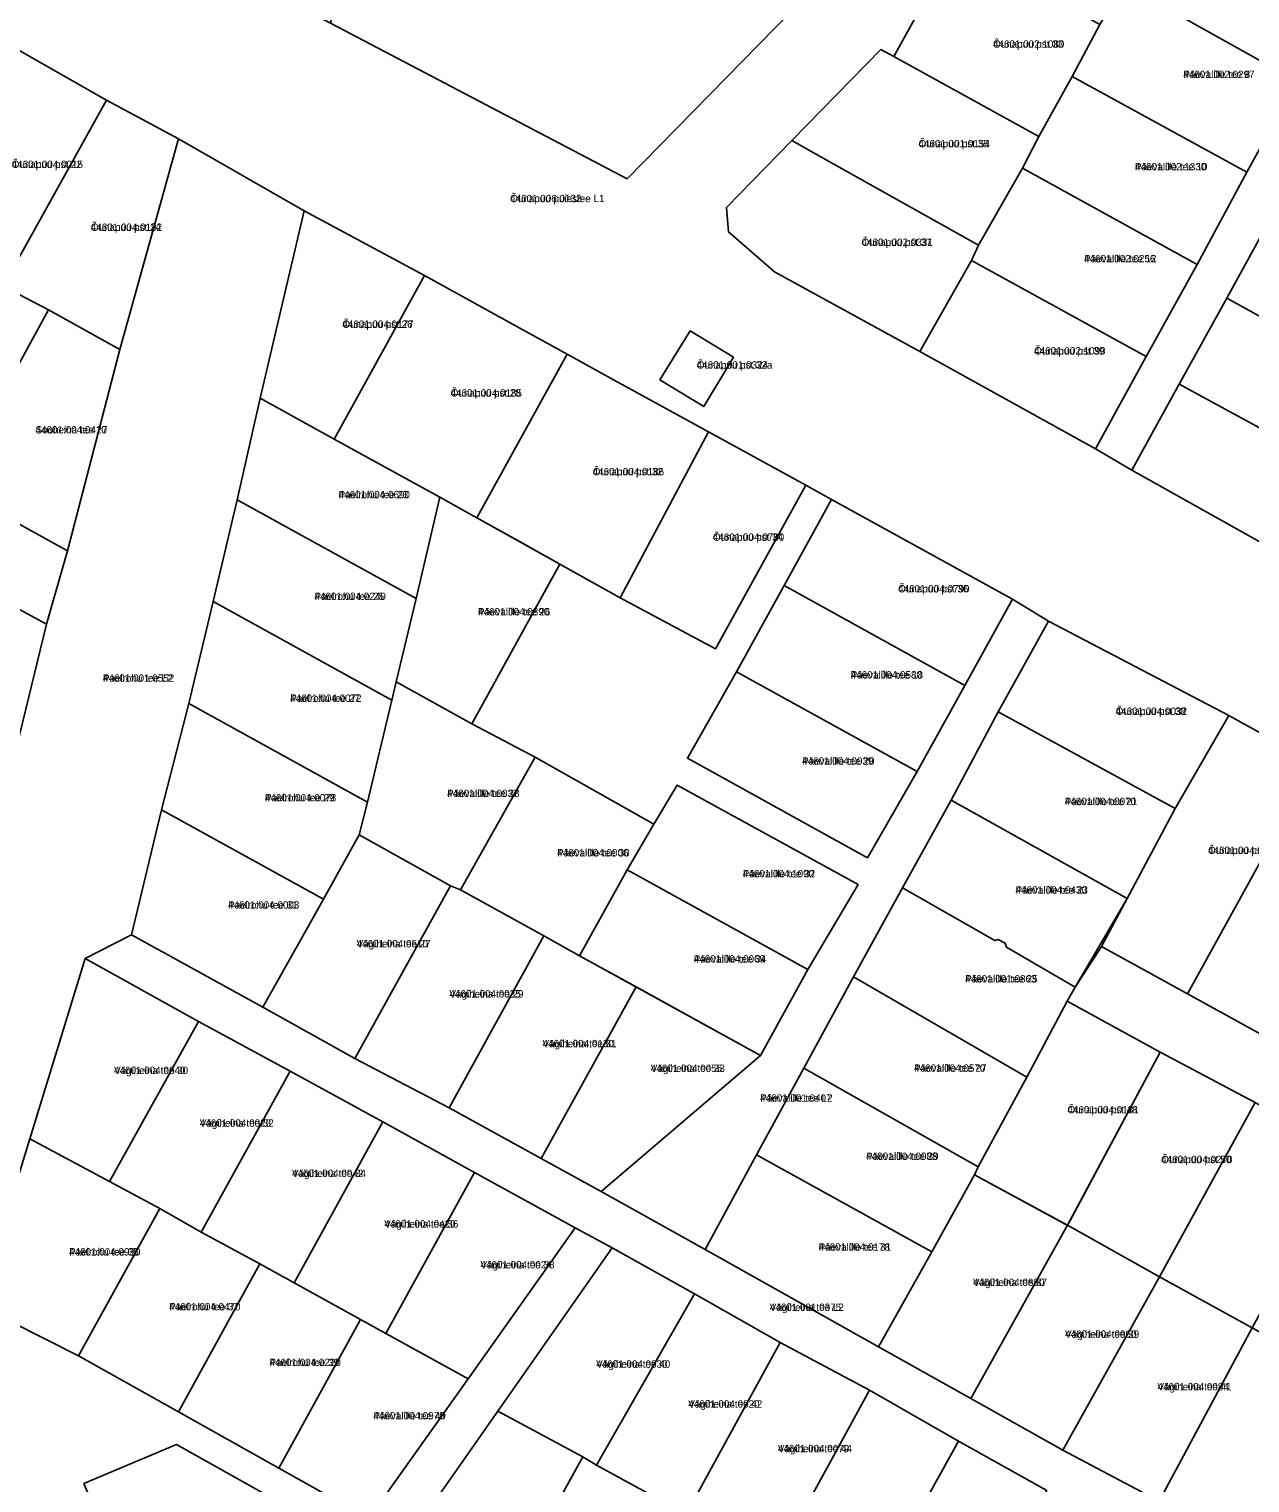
# Model space of a CAD drawing. Extents: x 551843 to 558501, y 6589003 to 6595718.
# Drawn here: x 552375.1 to 552623.4, y 6593188.1 to 6593483.8 of the extents above; entities that cross this region are included whole.
import ezdxf

# ---------------------------------------------------------------- set-up
doc = ezdxf.new("R2010")
doc.units = 0
for name, color, linetype in [('L_AADRESS', 7, 'Continuous'), ('PIIR', 7, 'Continuous'), ('TUNNUS', 7, 'Continuous')]:
    doc.layers.add(name, color=color, linetype=linetype)

msp = doc.modelspace()

# ---------------------------------------------------------------- linework, layer by layer
at = {"layer": 'PIIR'}
for points in [[(552461.93, 6593587.77), (552467.7, 6593633.22), (552490.58, 6593596.62), (552513.02, 6593563.94), (552517.24, 6593555.3), (552536.83, 6593523.16), (552546.96, 6593504.67), (552496.72, 6593453.35), (552436.41, 6593485.01), (552438.47, 6593493.3), (552506.38, 6593512.78), (552500.93, 6593521.97)], [(552660.92, 6593544.41), (552681.3, 6593543.01), (552676.56, 6593534.11), (552667.17, 6593516.83), (552657.46, 6593498.94), (552647.84, 6593481.41), (552638.03, 6593464.12), (552628.37, 6593446.6), (552618.71, 6593429.08), (552609.04, 6593411.57), (552599.39, 6593394.06), (552591.99, 6593398.44), (552602.33, 6593417.19), (552612.65, 6593435.92), (552622.77, 6593454.66), (552632.95, 6593473.18), (552643.15, 6593492.04), (552653.7, 6593510.58), (552664.72, 6593530.92)], [(552607.91, 6593511.51), (552643.15, 6593492.04), (552632.95, 6593473.18), (552597.6, 6593492.97)], [(552558.69, 6593492.22), (552568.76, 6593498.06), (552592.89, 6593484.72), (552587.23, 6593474.17), (552580.47, 6593461.92), (552550.96, 6593478.21)], [(552597.6, 6593492.97), (552632.95, 6593473.18), (552622.77, 6593454.66), (552587.23, 6593474.17), (552592.89, 6593484.72)], [(552390.85, 6593469.35), (552369.79, 6593431.47), (552352.22, 6593441.78), (552373.17, 6593479.39)], [(552538.8, 6593456.31), (552530.2, 6593461.12), (552548.33, 6593479.66), (552550.96, 6593478.21), (552580.47, 6593461.92), (552577.14, 6593455.51), (552568.22, 6593439.82)], [(552612.65, 6593435.92), (552577.14, 6593455.51), (552580.47, 6593461.92), (552587.23, 6593474.17), (552622.77, 6593454.66)], [(552390.85, 6593469.35), (552405.48, 6593461.46), (552393.51, 6593418.63), (552379.05, 6593426.69), (552369.79, 6593431.47)], [(552530.2, 6593461.12), (552538.8, 6593456.31), (552568.22, 6593439.82), (552566.77, 6593436.73), (552556.28, 6593418.23), (552526.73, 6593434.43), (552517.32, 6593442.54), (552516.91, 6593447.52)], [(552566.77, 6593436.73), (552568.22, 6593439.82), (552577.14, 6593455.51), (552612.65, 6593435.92), (552602.33, 6593417.19)], [(552431.04, 6593446.79), (552455.52, 6593433.66), (552437.12, 6593400.38), (552422.07, 6593408.73)], [(552628.37, 6593446.6), (552666.01, 6593425.83), (552656.34, 6593408.3), (552618.71, 6593429.08)], [(552340.46, 6593401.09), (552360.31, 6593437.03), (552369.79, 6593431.47), (552379.05, 6593426.69), (552359.28, 6593390.69)], [(552591.99, 6593398.44), (552556.28, 6593418.23), (552566.77, 6593436.73), (552602.33, 6593417.19)], [(552455.52, 6593433.66), (552474.9, 6593422.98), (552484.55, 6593417.65), (552466.18, 6593384.41), (552458.62, 6593388.56), (552456.51, 6593389.72), (552437.12, 6593400.38)], [(552656.34, 6593408.3), (552646.71, 6593391.12), (552609.04, 6593411.57), (552618.71, 6593429.08)], [(552382.87, 6593377.65), (552359.28, 6593390.69), (552379.05, 6593426.69), (552393.51, 6593418.63)], [(552509.57, 6593422.41), (552503.41, 6593412.42), (552512.3, 6593406.99), (552518.37, 6593417.03)], [(552503.41, 6593412.42), (552509.57, 6593422.41), (552518.37, 6593417.03), (552512.3, 6593406.99)], [(552484.55, 6593417.65), (552494.11, 6593412.4), (552513.28, 6593401.86), (552495.29, 6593368.14), (552483.05, 6593374.98), (552475.59, 6593379.15), (552466.18, 6593384.41)], [(552599.39, 6593394.06), (552609.04, 6593411.57), (552646.71, 6593391.12), (552637.14, 6593372.95)], [(552437.12, 6593400.38), (552456.51, 6593389.72), (552458.62, 6593388.56), (552453.78, 6593367.98), (552417.43, 6593388.03), (552422.07, 6593408.73)], [(552513.28, 6593401.86), (552533.05, 6593391.02), (552514.69, 6593357.76), (552495.29, 6593368.14)], [(552575.08, 6593367.81), (552582.45, 6593363.33), (552572.21, 6593344.94), (552562.61, 6593326.99), (552552.74, 6593309.12), (552542.8, 6593291.01), (552532.7, 6593272.48), (552523.02, 6593254.85), (552512.63, 6593235.58), (552491.42, 6593247.35), (552523.85, 6593275.06), (552533.48, 6593292.53), (552543.69, 6593309.78), (552506.88, 6593330), (552502.18, 6593322.06), (552478.05, 6593335.69), (552465.14, 6593342.5), (552483.05, 6593374.98), (552495.29, 6593368.14), (552514.69, 6593357.76), (552533.05, 6593391.02), (552538.3, 6593388.12), (552528.64, 6593370.6), (552518.97, 6593353.08), (552509, 6593335.48), (552545.59, 6593315.26), (552555.75, 6593332.79), (552565.42, 6593350.3)], [(552417.43, 6593388.03), (552453.78, 6593367.98), (552449.72, 6593351), (552448.83, 6593347.28), (552412.49, 6593367.33)], [(552465.14, 6593342.5), (552449.72, 6593351), (552453.78, 6593367.98), (552458.62, 6593388.56), (552466.18, 6593384.41), (552483.05, 6593374.98)], [(552575.08, 6593367.81), (552565.42, 6593350.3), (552528.64, 6593370.6), (552538.3, 6593388.12)], [(552371.96, 6593335.44), (552340.89, 6593352.26), (552344.77, 6593359.49), (552353.84, 6593376.18), (552378.6, 6593362.77)], [(552555.75, 6593332.79), (552518.97, 6593353.08), (552528.64, 6593370.6), (552565.42, 6593350.3)], [(552407.55, 6593346.63), (552412.49, 6593367.33), (552448.83, 6593347.28), (552443.89, 6593326.58)], [(552619.09, 6593344.16), (552608.23, 6593325.27), (552572.21, 6593344.94), (552582.45, 6593363.33)], [(552555.75, 6593332.79), (552545.59, 6593315.26), (552509, 6593335.48), (552518.97, 6593353.08)], [(552478.05, 6593335.69), (552462.82, 6593308.7), (552460.81, 6593309.52), (552442.19, 6593319.88), (552443.89, 6593326.58), (552448.83, 6593347.28), (552449.72, 6593351), (552465.14, 6593342.5)], [(552402, 6593324.96), (552407.55, 6593346.63), (552443.89, 6593326.58), (552442.19, 6593319.88), (552434.94, 6593306.8)], [(552562.61, 6593326.99), (552572.21, 6593344.94), (552608.23, 6593325.27), (552598.46, 6593306.95)], [(552608.23, 6593325.27), (552619.09, 6593344.16), (552636.6, 6593334.49), (552610.7, 6593287.57), (552593.19, 6593297.23), (552598.46, 6593306.95)], [(552502.18, 6593322.06), (552496.71, 6593312.81), (552487.07, 6593295.33), (552479.79, 6593299.35), (552462.82, 6593308.7), (552478.05, 6593335.69)], [(552610.7, 6593287.57), (552636.6, 6593334.49), (552654.11, 6593324.83), (552628.2, 6593277.92)], [(552533.48, 6593292.53), (552496.71, 6593312.81), (552502.18, 6593322.06), (552506.88, 6593330), (552543.69, 6593309.78)], [(552402, 6593324.96), (552434.94, 6593306.8), (552432.99, 6593303.27), (552422.61, 6593284.84), (552395.93, 6593299.54)], [(552552.74, 6593309.12), (552562.61, 6593326.99), (552598.46, 6593306.95), (552587.87, 6593288.91), (552573.89, 6593297.04), (552573.63, 6593297.87), (552572.22, 6593298.6), (552571.49, 6593298.41)], [(552441.37, 6593274.44), (552422.61, 6593284.84), (552432.99, 6593303.27), (552434.94, 6593306.8), (552442.19, 6593319.88), (552460.81, 6593309.52)], [(552533.48, 6593292.53), (552523.85, 6593275.06), (552487.07, 6593295.33), (552496.71, 6593312.81)], [(552479.79, 6593299.35), (552460.51, 6593264.41), (552441.37, 6593274.44), (552460.81, 6593309.52), (552462.82, 6593308.7)], [(552542.8, 6593291.01), (552552.74, 6593309.12), (552571.49, 6593298.41), (552572.22, 6593298.6), (552573.63, 6593297.87), (552573.89, 6593297.04), (552587.87, 6593288.91), (552586.23, 6593286.09), (552578.01, 6593270.63)], [(552460.51, 6593264.41), (552479.79, 6593299.35), (552487.07, 6593295.33), (552498.53, 6593289.01), (552479.25, 6593254.07)], [(552409.54, 6593281.96), (552391.45, 6593249.38), (552375.2, 6593258.06), (552386.47, 6593294.75)], [(552578.01, 6593270.63), (552568.14, 6593252.42), (552532.7, 6593272.48), (552542.8, 6593291.01)], [(552491.42, 6593247.35), (552479.25, 6593254.07), (552498.53, 6593289.01), (552523.85, 6593275.06)], [(552586.23, 6593286.09), (552605.17, 6593275.73), (552586.75, 6593241.36), (552586.29, 6593240.49), (552585.98, 6593240.66), (552567.41, 6593250.78), (552568.14, 6593252.42), (552578.01, 6593270.63)], [(552428.15, 6593271.85), (552410.08, 6593239.1), (552401.64, 6593243.89), (552391.45, 6593249.38), (552409.54, 6593281.96)], [(552624.44, 6593265.44), (552605.01, 6593230), (552586.29, 6593240.49), (552605.17, 6593275.73)], [(552447.05, 6593261.54), (552428.98, 6593228.79), (552422.03, 6593232.63), (552410.08, 6593239.1), (552428.15, 6593271.85)], [(552532.7, 6593272.48), (552568.14, 6593252.42), (552567.41, 6593250.78), (552558.69, 6593235.1), (552523.02, 6593254.85)], [(552605.01, 6593230), (552624.44, 6593265.44), (552642.91, 6593254.69), (552623.85, 6593219.65)], [(552465.69, 6593251.26), (552447.62, 6593218.52), (552442.52, 6593221.33), (552428.98, 6593228.79), (552447.05, 6593261.54)], [(552391.45, 6593249.38), (552401.64, 6593243.89), (552385.13, 6593213.96), (552364.8, 6593224.2), (552375.2, 6593258.06)], [(552523.02, 6593254.85), (552558.69, 6593235.1), (552547.87, 6593215.81), (552512.63, 6593235.58)], [(552486.17, 6593239.97), (552464.37, 6593209.28), (552447.62, 6593218.52), (552465.69, 6593251.26)], [(552586.29, 6593240.49), (552566.62, 6593205.29), (552547.87, 6593215.81), (552558.69, 6593235.1), (552567.41, 6593250.78)], [(552385.13, 6593213.96), (552401.64, 6593243.89), (552410.08, 6593239.1), (552422.03, 6593232.63), (552405.44, 6593202.57)], [(552605.01, 6593230), (552585.36, 6593194.77), (552566.62, 6593205.29), (552586.29, 6593240.49)], [(552493.66, 6593235.93), (552510.45, 6593226.58), (552490.49, 6593191.68), (552487.73, 6593193.41), (552470.42, 6593202.7)], [(552405.44, 6593202.57), (552422.03, 6593232.63), (552428.98, 6593228.79), (552442.52, 6593221.33), (552425.85, 6593191.12)], [(552604.93, 6593184.4), (552585.36, 6593194.77), (552605.01, 6593230), (552623.85, 6593219.65)], [(552506.51, 6593182.95), (552490.49, 6593191.68), (552510.45, 6593226.58), (552527.83, 6593216.68), (552508.74, 6593181.73)], [(552464.37, 6593209.28), (552444.18, 6593180.85), (552425.85, 6593191.12), (552442.52, 6593221.33)], [(552604.93, 6593184.4), (552623.85, 6593219.65), (552642.95, 6593208.95), (552633.87, 6593192.76), (552623.45, 6593174.45)], [(552527.83, 6593216.68), (552546.04, 6593206.94), (552526.86, 6593171.83), (552508.74, 6593181.73)], [(552546.04, 6593206.94), (552564.14, 6593196.6), (552544.78, 6593161.74), (552543.64, 6593162.38), (552526.86, 6593171.83)], [(552487.73, 6593193.41), (552469.23, 6593159.9), (552448.56, 6593171.5), (552470.42, 6593202.7)], [(552405.09, 6593195.89), (552435.14, 6593179.03), (552396.8, 6593162.89), (552386.24, 6593187.95)], [(552582.11, 6593186.56), (552562.82, 6593151.76), (552561.98, 6593152.18), (552544.78, 6593161.74), (552564.14, 6593196.6)], [(552506.51, 6593182.95), (552487.85, 6593149.45), (552469.23, 6593159.9), (552487.73, 6593193.41), (552490.49, 6593191.68)]]:
    msp.add_lwpolyline(points, close=True, dxfattribs=at)
for points in [[(552412.99, 6593497.3), (552496.72, 6593453.35), (552546.96, 6593504.67)], [(552558.69, 6593492.22), (552550.96, 6593478.21), (552548.33, 6593479.66), (552530.2, 6593461.12), (552516.91, 6593447.52), (552517.32, 6593442.54), (552526.73, 6593434.43), (552556.28, 6593418.23), (552591.99, 6593398.44), (552599.39, 6593394.06), (552637.14, 6593372.95)], [(552636.6, 6593334.49), (552619.09, 6593344.16), (552582.45, 6593363.33), (552575.08, 6593367.81), (552538.3, 6593388.12), (552533.05, 6593391.02), (552513.28, 6593401.86), (552494.11, 6593412.4), (552484.55, 6593417.65), (552474.9, 6593422.98), (552455.52, 6593433.66), (552431.04, 6593446.79), (552405.48, 6593461.46), (552390.85, 6593469.35), (552373.17, 6593479.39)], [(552371.96, 6593335.44), (552378.6, 6593362.77), (552382.87, 6593377.65), (552393.51, 6593418.63), (552405.48, 6593461.46), (552431.04, 6593446.79), (552422.07, 6593408.73), (552417.43, 6593388.03), (552412.49, 6593367.33), (552407.55, 6593346.63), (552402, 6593324.96), (552395.93, 6593299.54), (552386.47, 6593294.75), (552375.2, 6593258.06), (552364.8, 6593224.2), (552385.13, 6593213.96), (552405.44, 6593202.57), (552425.85, 6593191.12), (552444.18, 6593180.85), (552464.37, 6593209.28), (552486.17, 6593239.97), (552493.66, 6593235.93), (552470.42, 6593202.7), (552448.56, 6593171.5)], [(552359.28, 6593390.69), (552382.87, 6593377.65), (552378.6, 6593362.77), (552353.84, 6593376.18)], [(552582.11, 6593186.56), (552564.14, 6593196.6), (552546.04, 6593206.94), (552527.83, 6593216.68), (552510.45, 6593226.58), (552493.66, 6593235.93), (552486.17, 6593239.97), (552465.69, 6593251.26), (552447.05, 6593261.54), (552428.15, 6593271.85), (552409.54, 6593281.96), (552386.47, 6593294.75), (552395.93, 6593299.54), (552422.61, 6593284.84), (552441.37, 6593274.44), (552460.51, 6593264.41), (552479.25, 6593254.07), (552491.42, 6593247.35), (552512.63, 6593235.58), (552547.87, 6593215.81), (552566.62, 6593205.29), (552585.36, 6593194.77), (552604.93, 6593184.4)], [(552624.44, 6593265.44), (552605.17, 6593275.73), (552586.23, 6593286.09), (552587.87, 6593288.91), (552593.19, 6593297.23), (552610.7, 6593287.57), (552628.2, 6593277.92)], [(552435.14, 6593179.03), (552405.09, 6593195.89), (552386.24, 6593187.95)]]:
    msp.add_lwpolyline(points, dxfattribs=at)

# ---------------------------------------------------------------- texts
at = {"layer": 'L_AADRESS'}
for s, p in [('Õunapuu pst 33', (552571.15, 6593479.99)), ('Päevalille tee 8', (552609.85, 6593473.82)), ('Õunapuu pst 35', (552556, 6593459.74)), ('Õunapuu pst 22', (552371.54, 6593455.53)), ('Päevalille tee 10', (552600.03, 6593455.05)), ('Õunapuu puiestee L1', (552472.93, 6593448.58)), ('Õunapuu pst 24', (552387.63, 6593442.74)), ('Õunapuu pst 37', (552544.4, 6593439.68)), ('Päevalille tee 12', (552589.67, 6593436.35)), ('Õunapuu pst 26', (552438.8, 6593423.02)), ('Õunapuu pst 39', (552579.53, 6593417.59)), ('Õunapuu pst 32a', (552510.89, 6593414.73)), ('Õunapuu pst 28', (552460.83, 6593409.04)), ('Sooheina tee 27', (552376.39, 6593401.54)), ('Õunapuu pst 32', (552489.73, 6593393.03)), ('Paelrohu tee 23', (552438.04, 6593388.36)), ('Õunapuu pst 34', (552514.17, 6593379.71)), ('Paelrohu tee 25', (552433.13, 6593367.66)), ('Õunapuu pst 36', (552551.85, 6593369.21)), ('Päevalille tee 26', (552466.38, 6593364.53)), ('Paelrohu tee L2', (552390.1, 6593351.04)), ('Päevalille tee 18', (552542.19, 6593351.7)), ('Paelrohu tee 27', (552428.19, 6593346.95)), ('Õunapuu pst 38', (552596.1, 6593344.3)), ('Päevalille tee 20', (552532.31, 6593334.17)), ('Paelrohu tee 29', (552423.05, 6593326.71)), ('Päevalille tee 28', (552460.12, 6593327.59)), ('Päevalille tee 21', (552585.74, 6593325.95)), ('Päevalille tee 30', (552482.5, 6593315.51)), ('Õunapuu pst 40', (552614.89, 6593316.02)), ('Päevalille tee 32', (552520.25, 6593311.27)), ('Päevalille tee 23', (552575.73, 6593307.95)), ('Paelrohu tee 31', (552415.55, 6593304.9)), ('Vägiheina tee 27', (552441.71, 6593297.03)), ('Päevalille tee 34', (552510.27, 6593293.93)), ('Päevalille tee 25', (552565.49, 6593289.88)), ('Vägiheina tee 29', (552460.58, 6593286.82)), ('Vägiheina tee 31', (552479.52, 6593276.71)), ('Vägiheina tee 30', (552392.37, 6593271.26)), ('Vägiheina tee 33', (552501.55, 6593271.68)), ('Päevalille tee 27', (552555.09, 6593271.72)), ('Päevalille tee L2', (552523.8, 6593265.64)), ('Õunapuu pst 48', (552586.29, 6593263.27)), ('Vägiheina tee 32', (552409.8, 6593260.54)), ('Päevalille tee 29', (552545.33, 6593253.79)), ('Õunapuu pst 50', (552605.36, 6593253.14)), ('Vägiheina tee 34', (552428.56, 6593250.32)), ('Vägiheina tee 36', (552447.33, 6593240.03)), ('Päevalille tee 31', (552535.68, 6593235.33)), ('Paelrohu tee 35', (552383.22, 6593234.35)), ('Vägiheina tee 38', (552466.89, 6593231.72)), ('Vägiheina tee 37', (552567.08, 6593228.15)), ('Paelrohu tee 37', (552403.58, 6593223.2)), ('Vägiheina tee L2', (552525.75, 6593223.08)), ('Vägiheina tee 39', (552585.81, 6593217.61)), ('Paelrohu tee 39', (552423.98, 6593211.86)), ('Vägiheina tee 40', (552490.44, 6593211.52)), ('Vägiheina tee 41', (552604.61, 6593206.92)), ('Vägiheina tee 42', (552509.16, 6593203.41)), ('Päevalille tee 40', (552445.11, 6593201.03)), ('Vägiheina tee 44', (552527.39, 6593194.34))]:
    msp.add_text(s, height=1.5, dxfattribs=at).set_placement(p)
at = {"layer": 'TUNNUS'}
for s, p in [('44601:002:1080', (552571.15, 6593479.99)), ('44601:002:0297', (552609.85, 6593473.82)), ('44601:001:0154', (552556, 6593459.74)), ('44601:004:0015', (552371.54, 6593455.53)), ('44601:002:1330', (552600.03, 6593455.05)), ('44601:006:0132', (552472.93, 6593448.58)), ('44601:004:0192', (552387.63, 6593442.74)), ('44601:002:0331', (552544.4, 6593439.68)), ('44601:002:0256', (552589.67, 6593436.35)), ('44601:004:0177', (552438.8, 6593423.02)), ('44601:002:1090', (552579.53, 6593417.59)), ('44601:001:0324', (552510.89, 6593414.73)), ('44601:004:0185', (552460.83, 6593409.04)), ('44601:004:0410', (552376.39, 6593401.54)), ('44601:004:0186', (552489.73, 6593393.03)), ('44601:004:0690', (552438.04, 6593388.36)), ('44601:004:0760', (552514.17, 6593379.71)), ('44601:004:0240', (552433.13, 6593367.66)), ('44601:004:0790', (552551.85, 6593369.21)), ('44601:004:0390', (552466.38, 6593364.53)), ('44601:001:0552', (552390.1, 6593351.04)), ('44601:004:0580', (552542.19, 6593351.7)), ('44601:004:0072', (552428.19, 6593346.95)), ('44601:004:0032', (552596.1, 6593344.3)), ('44601:004:0039', (552532.31, 6593334.17)), ('44601:004:0078', (552423.05, 6593326.71)), ('44601:004:0037', (552460.12, 6593327.59)), ('44601:004:0070', (552585.74, 6593325.95)), ('44601:004:0006', (552482.5, 6593315.51)), ('44601:004:0230', (552614.89, 6593316.02)), ('44601:004:1090', (552520.25, 6593311.27)), ('44601:004:0430', (552575.73, 6593307.95)), ('44601:004:0003', (552415.55, 6593304.9)), ('44601:004:0510', (552441.71, 6593297.03)), ('44601:004:0069', (552510.27, 6593293.93)), ('44601:001:0863', (552565.49, 6593289.88)), ('44601:004:0025', (552460.58, 6593286.82)), ('44601:004:0130', (552479.52, 6593276.71)), ('44601:004:0840', (552392.37, 6593271.26)), ('44601:004:0055', (552501.55, 6593271.68)), ('44601:004:0570', (552555.09, 6593271.72)), ('44601:001:0407', (552523.8, 6593265.64)), ('44601:004:0181', (552586.29, 6593263.27)), ('44601:004:0023', (552409.8, 6593260.54)), ('44601:004:0088', (552545.33, 6593253.79)), ('44601:004:0270', (552605.36, 6593253.14)), ('44601:004:0042', (552428.56, 6593250.32)), ('44601:004:0420', (552447.33, 6593240.03)), ('44601:004:0178', (552535.68, 6593235.33)), ('44601:004:0930', (552383.22, 6593234.35)), ('44601:004:0024', (552466.89, 6593231.72)), ('44601:004:0890', (552567.08, 6593228.15)), ('44601:004:0470', (552403.58, 6593223.2)), ('44601:001:0375', (552525.75, 6593223.08)), ('44601:004:0960', (552585.81, 6593217.61)), ('44601:004:0220', (552423.98, 6593211.86)), ('44601:004:0030', (552490.44, 6593211.52)), ('44601:004:0084', (552604.61, 6593206.92)), ('44601:004:0020', (552509.16, 6593203.41)), ('44601:004:0970', (552445.11, 6593201.03)), ('44601:004:0079', (552527.39, 6593194.34))]:
    msp.add_text(s, height=1.5, dxfattribs=at).set_placement(p)

doc.saveas('drawing.dxf')
